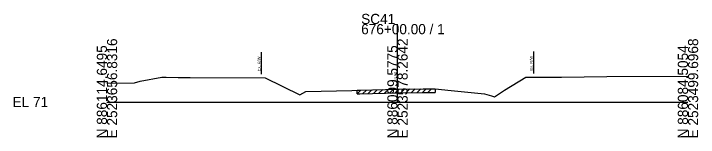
# Model space of a CAD drawing. Extents: x -26 to 183, y -10 to 24021.
# Drawn here: x -25.7 to 162.8, y 8490.3 to 8524.3 of the extents above; entities that cross this region are included whole.
import ezdxf

# ---------------------------------------------------------------- set-up
doc = ezdxf.new("R2010")
doc.units = 0
for name, color, linetype in [('RD_GPK_XS_Cell', 7, 'Continuous'), ('RD_XS_ExGround', 7, 'Continuous'), ('RD_XS_ExPaveRet', 7, 'Continuous'), ('RD_XS_ExRW', 7, 'Continuous'), ('RD_XS_TX_Elev_EX', 7, 'Continuous')]:
    doc.layers.add(name, color=color, linetype=linetype)

msp = doc.modelspace()

# ---------------------------------------------------------------- linework, layer by layer
at = {"layer": 'RD_GPK_XS_Cell'}
for p, q in [((80, 8500), (80, 8521.45)), ((0, 8500), (80, 8500)), ((80, 8500), (160, 8500))]:
    msp.add_line(p, q, dxfattribs=at)
at = {"layer": 'RD_XS_ExGround'}
for p, q in [((9.18, 8505.75), (15.11, 8506.82)), ((15.11, 8506.82), (16.3, 8506.82)), ((16.3, 8506.82), (19.62, 8506.78)), ((19.62, 8506.78), (22.87, 8506.75)), ((22.87, 8506.75), (43.52, 8506.68)), ((43.52, 8506.68), (53.07, 8501.96)), ((109.51, 8503.25), (115.31, 8506.87)), ((115.31, 8506.87), (125.18, 8506.87)), ((125.18, 8506.87), (137.63, 8506.99)), ((137.63, 8506.99), (160, 8507.15)), ((0, 8505.2), (7.58, 8505.26)), ((7.58, 8505.26), (9.18, 8505.75)), ((53.07, 8501.96), (54.76, 8502.91)), ((54.76, 8502.91), (67.41, 8503.18)), ((67.41, 8503.18), (68.9, 8503.23)), ((68.9, 8503.23), (69.65, 8503.26)), ((69.65, 8503.26), (80.15, 8503.57)), ((80.15, 8503.57), (87.04, 8503.61)), ((87.04, 8503.61), (90.41, 8503.63)), ((90.41, 8503.63), (94.82, 8503.17)), ((94.82, 8503.17), (103.92, 8502.25)), ((106.76, 8501.44), (109.51, 8503.25)), ((103.92, 8502.25), (105.85, 8501.71)), ((105.85, 8501.71), (106.76, 8501.44))]:
    msp.add_line(p, q, dxfattribs=at)
at = {"layer": 'RD_XS_ExPaveRet'}
for p, q in [((68.9, 8502.23), (69.93, 8503.27)), ((68.9, 8502.23), (68.9, 8503.23)), ((70.4, 8502.28), (71.43, 8503.31)), ((71.9, 8502.32), (72.93, 8503.35)), ((73.4, 8502.37), (74.43, 8503.4)), ((74.9, 8502.41), (75.93, 8503.44)), ((76.4, 8502.46), (77.43, 8503.49)), ((77.9, 8502.5), (78.93, 8503.53)), ((79.4, 8502.55), (80.42, 8503.57)), ((80.9, 8502.57), (81.9, 8503.58)), ((82.4, 8502.58), (83.4, 8503.59)), ((83.9, 8502.59), (84.9, 8503.59)), ((85.4, 8502.6), (86.4, 8503.6)), ((86.9, 8502.6), (87.9, 8503.61)), ((88.4, 8502.61), (89.4, 8503.62)), ((90.41, 8503.63), (90.41, 8502.63)), ((68.9, 8502.23), (69.65, 8502.26)), ((69.65, 8502.26), (80.15, 8502.57)), ((80.15, 8502.57), (87.04, 8502.61)), ((87.04, 8502.61), (90.41, 8502.63))]:
    msp.add_line(p, q, dxfattribs=at)
at = {"layer": 'RD_XS_ExRW'}
for p, q in [((42.5, 8513.69), (42.5, 8507.69)), ((117.5, 8513.87), (117.5, 8507.87))]:
    msp.add_line(p, q, dxfattribs=at)

# ---------------------------------------------------------------- texts
at = {"layer": 'RD_GPK_XS_Cell'}
for s, p in [('SC41', (70, 8521.45)), ('676+00.00 / 1', (70, 8518.65)), ('EL 71', (-26, 8498.6))]:
    msp.add_text(s, height=2.8, dxfattribs=at).set_placement(p)
for s, p in [('E 2523656.8316', (2.8, 8490)), ('E 2523578.2642', (82.8, 8490)), ('E 2523499.6968', (162.8, 8490)), ('N 886114.6495', (0, 8490)), ('N 886099.5775', (80, 8490)), ('N 886084.5054', (160, 8490))]:
    msp.add_text(s, height=2.8, rotation=90, dxfattribs=at).set_placement(p)
at = {"layer": 'RD_XS_ExRW'}
for p in [(42.25, 8508.47), (117.25, 8508.66)]:
    msp.add_text('Ex. R/W ', height=0.8, rotation=90, dxfattribs=at).set_placement(p)
at = {"layer": 'RD_XS_TX_Elev_EX'}
msp.add_text('74.57', height=0.8, rotation=90, dxfattribs=at).set_placement((79.9, 8505.57))

doc.saveas('drawing.dxf')
